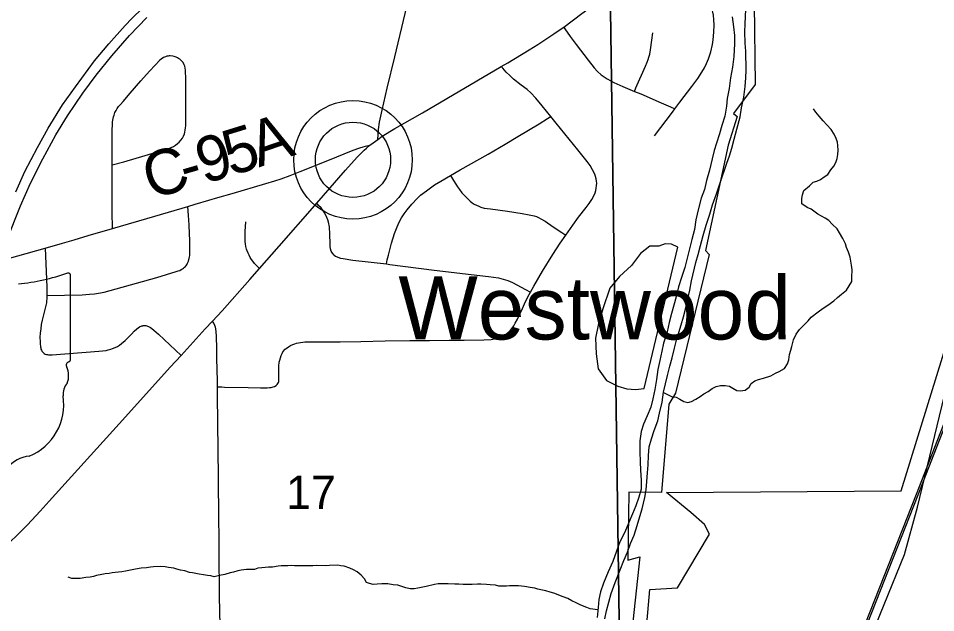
# Model space of a CAD drawing. Extents: x 0 to 34, y 0 to 22.
# Drawn here: x 18.513 to 19.665, y 11.815 to 12.561 of the extents above; entities that cross this region are included whole.
import ezdxf

# ---------------------------------------------------------------- set-up
doc = ezdxf.new("R2010")
doc.units = 0
for name, color, linetype in [('GM_X_Corporation', 7, 'Continuous'), ('GM_X_County_Road', 7, 'Continuous'), ('GM_X_County_Road_Text', 7, 'Continuous'), ('GM_X_Major_River', 7, 'Continuous'), ('GM_X_Minor_Lake', 7, 'Continuous'), ('GM_X_Minor_River', 7, 'Continuous'), ('GM_X_Rail_Line', 7, 'Continuous'), ('GM_X_Section', 7, 'Continuous'), ('GM_X_Section_Text', 7, 'Continuous'), ('GM_X_State_Route', 7, 'Continuous'), ('GM_X_State_Shield', 7, 'Continuous'), ('GM_X_Township_Road', 7, 'Continuous'), ('GM_X_Unincorporated', 7, 'Continuous'), ('GM_X_Unincorporated_Location', 7, 'Continuous'), ('GM_X_Unincorporated_Text', 7, 'Continuous')]:
    doc.layers.add(name, color=color, linetype=linetype)

msp = doc.modelspace()

# ---------------------------------------------------------------- linework, layer by layer
at = {"layer": 'GM_X_Corporation'}
for points in [[(19.4365, 12.5791), (19.4378, 12.4781), (19.4109, 12.4418), (19.4155, 12.438), (19.404, 12.4018), (19.3756, 12.2698), (19.38, 12.2645), (19.338, 12.0907), (19.3296, 12.0768), (19.3202, 11.9662), (19.2795, 11.9663), (19.278, 11.8812), (19.2931, 11.8855), (19.2621, 11.5978)], [(19.2866, 11.6238), (19.3057, 11.8444), (19.3404, 11.8464), (19.3805, 11.9139), (19.3744, 11.9259), (19.357, 11.9408), (19.3266, 11.9659), (19.6212, 11.9681), (19.6857, 12.1764)]]:
    msp.add_lwpolyline(points, dxfattribs=at)
at = {"layer": 'GM_X_County_Road'}
msp.add_line((18.4879, 12.2563), (18.5465, 12.2726), dxfattribs=at)
for points in [[(18.9641, 12.409), (18.9645, 12.4151), (18.9649, 12.4214), (18.9663, 12.4307), (18.9695, 12.446), (18.9758, 12.4733), (18.9854, 12.5127), (18.9986, 12.567), (19.0077, 12.6063)], [(19.1975, 12.55), (19.2204, 12.567), (19.2504, 12.5891), (19.2598, 12.5956), (19.2682, 12.6011), (19.2718, 12.6032)], [(19.1192, 12.5006), (19.1273, 12.5054), (19.1542, 12.5215), (19.165, 12.5284), (19.1738, 12.5339), (19.1852, 12.5415), (19.1968, 12.5495), (19.1975, 12.55)], [(18.9641, 12.409), (18.9698, 12.413), (18.9857, 12.4226), (19.0202, 12.4426), (19.1192, 12.5006)], [(18.954, 12.4017), (18.9583, 12.4049), (18.9641, 12.409)], [(18.7255, 12.325), (18.7348, 12.3277), (18.7519, 12.3329), (18.7635, 12.3362), (18.7813, 12.3414), (18.8236, 12.3536), (18.835, 12.357), (18.8427, 12.3596), (18.8543, 12.3639), (18.8668, 12.3687), (18.9015, 12.3825), (18.9332, 12.3954), (18.9414, 12.3984), (18.9459, 12.3999), (18.9487, 12.4006), (18.954, 12.4017)], [(18.8875, 12.329), (18.9236, 12.3706), (18.9383, 12.3867), (18.9425, 12.3912), (18.9446, 12.3932), (18.9471, 12.3955), (18.95, 12.3983), (18.954, 12.4017)], [(18.631, 12.2974), (18.6842, 12.3129), (18.7255, 12.325)], [(18.8155, 12.247), (18.8403, 12.2753), (18.8851, 12.3262), (18.8875, 12.329)], [(18.5465, 12.2726), (18.5682, 12.2789), (18.5831, 12.2832), (18.6006, 12.2885), (18.631, 12.2974)], [(18.7567, 12.1812), (18.7686, 12.1941), (18.8036, 12.2335), (18.8155, 12.247)], [(18.7171, 12.1378), (18.7476, 12.1713), (18.7567, 12.1812)], [(18.2625, 11.683), (18.2699, 11.6903), (18.3514, 11.7649), (18.4086, 11.8174), (18.4384, 11.8446), (18.5022, 11.9035), (18.5117, 11.9129), (18.5242, 11.9253), (18.5401, 11.9425), (18.5514, 11.9551), (18.6473, 12.061), (18.7036, 12.1231), (18.7171, 12.1378)]]:
    msp.add_lwpolyline(points, dxfattribs=at)
at = {"layer": 'GM_X_Major_River'}
for points in [[(19.2491, 11.8073), (19.2513, 11.8176), (19.2543, 11.8286), (19.2572, 11.8392), (19.262, 11.8529), (19.2684, 11.8689), (19.2732, 11.8807), (19.2777, 11.8913), (19.2814, 11.902), (19.2859, 11.9123), (19.2896, 11.9248), (19.2933, 11.9358), (19.2959, 11.9457), (19.2996, 11.9598), (19.301, 11.9693), (19.3021, 11.9799), (19.3028, 11.9905), (19.3034, 12.0008), (19.3041, 12.0125), (19.3048, 12.0235), (19.3078, 12.0334), (19.3111, 12.0437), (19.3156, 12.0558), (19.3178, 12.0657), (19.3211, 12.0794), (19.3229, 12.0919), (19.3255, 12.1022), (19.3277, 12.1128), (19.3306, 12.1246), (19.3336, 12.1352), (19.3365, 12.147), (19.3391, 12.1573), (19.345, 12.1763), (19.348, 12.1865), (19.3509, 12.1979), (19.3535, 12.209), (19.3557, 12.22), (19.3579, 12.2317), (19.3634, 12.2545), (19.3664, 12.2648), (19.3693, 12.2758), (19.3727, 12.2884), (19.3764, 12.3013), (19.3812, 12.3154), (19.3845, 12.3268), (19.3893, 12.3408), (19.3934, 12.3534), (19.4023, 12.3792), (19.4057, 12.3887), (19.4086, 12.3982), (19.4116, 12.4093), (19.4149, 12.4218), (19.419, 12.4374), (19.4208, 12.4488), (19.4237, 12.4621), (19.4255, 12.4757), (19.4262, 12.4864), (19.4265, 12.4962), (19.4264, 12.5197), (19.4252, 12.53), (19.4251, 12.544), (19.4254, 12.5542), (19.4264, 12.5721)], [(19.409, 12.5628), (19.4106, 12.5503), (19.4118, 12.5397), (19.4119, 12.5291), (19.4113, 12.5132), (19.4095, 12.4999), (19.4069, 12.4862), (19.4051, 12.4729), (19.4029, 12.4604), (19.4018, 12.4509), (19.3997, 12.4384), (19.3959, 12.4266), (19.393, 12.4163), (19.3893, 12.4045), (19.3863, 12.395), (19.3841, 12.3848), (19.3804, 12.3703), (19.3767, 12.3574)], [(19.3767, 12.3574), (19.3742, 12.3464), (19.3701, 12.3354), (19.3667, 12.3225), (19.3634, 12.308), (19.3616, 12.2962), (19.3583, 12.2833), (19.3498, 12.2484), (19.3454, 12.2358), (19.3417, 12.224), (19.3387, 12.2115), (19.3358, 12.2012), (19.3328, 12.1906), (19.3299, 12.1792), (19.3273, 12.1678), (19.3228, 12.1534), (19.3206, 12.1435), (19.3181, 12.1317), (19.3159, 12.1203), (19.3141, 12.1078), (19.3119, 12.0953), (19.3093, 12.0835), (19.3071, 12.0732), (19.3023, 12.0622), (19.2978, 12.0519), (19.2948, 12.0424), (19.293, 12.031), (19.2931, 12.017), (19.2936, 12.0045), (19.294, 11.9942), (19.2949, 11.9814), (19.2946, 11.9704), (19.292, 11.9601), (19.2879, 11.9494), (19.2838, 11.9392), (19.2793, 11.9285), (19.2741, 11.9163), (19.2681, 11.9042), (19.2637, 11.8924), (19.2592, 11.8794), (19.2532, 11.8665), (19.2477, 11.8524), (19.2439, 11.8414), (19.2417, 11.8319), (19.2407, 11.8217), (19.2396, 11.8091)]]:
    msp.add_lwpolyline(points, dxfattribs=at)
at = {"layer": 'GM_X_Minor_Lake'}
for points in [[(19.3409, 12.2737), (19.333, 12.2778), (19.325, 12.2781), (19.3171, 12.2751), (19.3057, 12.275), (19.294, 12.2658), (19.2828, 12.2509), (19.2677, 12.2371), (19.2553, 12.2226), (19.2468, 12.1964), (19.2409, 12.1759), (19.2376, 12.1595), (19.2381, 12.1402), (19.2409, 12.1213), (19.2512, 12.1066), (19.2653, 12.0995), (19.277, 12.0961), (19.2876, 12.0954), (19.2986, 12.0967)], [(19.2986, 12.0967), (19.3409, 12.2737)]]:
    msp.add_lwpolyline(points, dxfattribs=at)
at = {"layer": 'GM_X_Minor_River'}
for points in [[(19.3228, 12.0917), (19.3337, 12.0859), (19.3387, 12.0856), (19.3433, 12.0833), (19.3483, 12.0804), (19.3532, 12.0789), (19.3578, 12.0801), (19.3634, 12.0832), (19.3687, 12.0863), (19.3733, 12.0898), (19.3789, 12.0929), (19.3838, 12.0964), (19.3891, 12.0991), (19.3944, 12.1004), (19.4001, 12.1004), (19.4055, 12.0994), (19.41, 12.0971), (19.415, 12.0942), (19.4196, 12.0935), (19.4253, 12.0943), (19.4302, 12.0982), (19.4328, 12.1028), (19.4373, 12.1062), (19.4422, 12.1078), (19.4483, 12.1094), (19.4574, 12.1126), (19.4634, 12.1157), (19.468, 12.1177), (19.4748, 12.1216), (19.4785, 12.1273), (19.4803, 12.1327), (19.481, 12.1391), (19.4828, 12.1448), (19.4839, 12.1494), (19.4861, 12.1574), (19.4894, 12.1647), (19.4935, 12.1704), (19.5044, 12.1816), (19.5082, 12.1862), (19.5172, 12.1928), (19.5232, 12.1974), (19.5293, 12.2009), (19.5368, 12.2067), (19.5413, 12.2106), (19.5462, 12.2148), (19.5526, 12.2198), (19.5593, 12.2306), (19.5592, 12.2363), (19.5595, 12.2454), (19.559, 12.2515), (19.557, 12.2613), (19.555, 12.2677), (19.5527, 12.2734), (19.5515, 12.2779), (19.548, 12.2847), (19.5437, 12.2919), (19.541, 12.2968), (19.5344, 12.3028), (19.5305, 12.3073), (19.5259, 12.3103), (19.5213, 12.3129), (19.5164, 12.3151), (19.5083, 12.3214), (19.503, 12.3236), (19.4964, 12.3281), (19.4967, 12.335), (19.4974, 12.3395), (19.4992, 12.3452), (19.506, 12.351), (19.5109, 12.3553), (19.5155, 12.3569), (19.52, 12.3588), (19.5245, 12.3623), (19.529, 12.365), (19.5331, 12.3708), (19.5365, 12.3754), (19.5391, 12.3803), (19.5409, 12.3853), (19.5416, 12.3903), (19.5423, 12.3956), (19.5419, 12.4013), (19.5411, 12.4058), (19.5395, 12.4104), (19.5371, 12.4156), (19.5332, 12.4217), (19.5278, 12.4273), (19.5232, 12.4326), (19.5182, 12.4382), (19.514, 12.4431), (19.5112, 12.4476)], [(19.2404, 11.8188), (19.2307, 11.8201), (19.2265, 11.8216), (19.2189, 11.8245), (19.2131, 11.8275), (19.2078, 11.8301), (19.2028, 11.833), (19.1967, 11.8352), (19.1852, 11.8396), (19.1806, 11.8411), (19.1753, 11.8426), (19.1711, 11.8433), (19.165, 11.8447), (19.1612, 11.8458), (19.1554, 11.8468), (19.1482, 11.8479), (19.1406, 11.8489), (19.1295, 11.8488), (19.1257, 11.8484), (19.1208, 11.8483), (19.1162, 11.8486), (19.112, 11.8497), (19.1052, 11.85), (19.1006, 11.8507), (19.0934, 11.851), (19.0892, 11.8509), (19.0827, 11.8504), (19.0759, 11.8507), (19.0713, 11.8507), (19.066, 11.851), (19.0607, 11.8509), (19.0523, 11.8516), (19.0401, 11.8514), (19.0352, 11.8506), (19.025, 11.8481), (19.0185, 11.8469), (19.0143, 11.8461), (19.0098, 11.8453), (19.0048, 11.8452), (18.9995, 11.8463), (18.9942, 11.8481), (18.9892, 11.8496), (18.9835, 11.8503), (18.9766, 11.8513), (18.9728, 11.8513), (18.969, 11.8516), (18.9633, 11.8511), (18.9584, 11.8507), (18.9538, 11.8518), (18.95, 11.8532), (18.9473, 11.8577), (18.9434, 11.8623), (18.9384, 11.8664), (18.9338, 11.869), (18.9292, 11.8712), (18.9219, 11.8734), (18.9178, 11.8741), (18.9139, 11.8748), (18.9037, 11.8746), (18.8987, 11.8742), (18.8873, 11.8744), (18.8824, 11.874), (18.8729, 11.8739), (18.8664, 11.8741), (18.8596, 11.8741), (18.8558, 11.8744), (18.8512, 11.8739), (18.8428, 11.8738), (18.839, 11.8734), (18.8318, 11.8725), (18.8269, 11.8725), (18.8185, 11.8716), (18.8136, 11.8712), (18.8094, 11.8696), (18.7992, 11.8694), (18.7927, 11.8686), (18.7885, 11.8678), (18.7828, 11.8662), (18.7787, 11.8654), (18.7719, 11.863), (18.7654, 11.8618), (18.7586, 11.8602), (18.7544, 11.8613), (18.7502, 11.862), (18.7452, 11.8627), (18.7399, 11.8637), (18.7315, 11.8651), (18.7277, 11.8658), (18.722, 11.8677), (18.7163, 11.8687), (18.7117, 11.8698), (18.7079, 11.8709), (18.7014, 11.8719), (18.6972, 11.8726), (18.6915, 11.873), (18.6827, 11.8728), (18.6786, 11.8724)], [(18.6786, 11.8724), (18.6736, 11.8716), (18.6672, 11.8711), (18.66, 11.8699), (18.6474, 11.8674), (18.6429, 11.8666), (18.6387, 11.8662), (18.6345, 11.8657), (18.6307, 11.8653), (18.6269, 11.8645), (18.622, 11.864), (18.6178, 11.8632), (18.611, 11.862), (18.6072, 11.8608), (18.603, 11.8596), (18.5977, 11.8592), (18.5905, 11.8583), (18.5802, 11.8582), (18.5753, 11.8596)]]:
    msp.add_lwpolyline(points, dxfattribs=at)
at = {"layer": 'GM_X_Rail_Line'}
for points in [[(18.7784, 9.1775), (18.7977, 9.2424), (18.8168, 9.3375), (18.9298, 9.894), (18.9918, 10.216), (19.0166, 10.3387), (19.0457, 10.4205), (19.1061, 10.5746), (19.3565, 11.2099), (19.4976, 11.5746), (19.6255, 11.8884), (19.6416, 11.9475), (19.8022, 12.6107)], [(19.3502, 11.2278), (19.6405, 11.9641), (19.7617, 12.2746)], [(19.3524, 11.227), (19.6427, 11.9632), (19.7639, 12.2737)]]:
    msp.add_lwpolyline(points, dxfattribs=at)
at = {"layer": 'GM_X_Section'}
for points in [[(18.2539, 12.6075), (19.256, 12.6012), (19.2699, 11.5992), (18.2587, 11.5914)], [(19.256, 12.6012), (20.265, 12.6049), (20.27, 11.6062), (19.2699, 11.5992)]]:
    msp.add_lwpolyline(points, close=True, dxfattribs=at)
at = {"layer": 'GM_X_State_Route'}
for points in [[(18.5095, 12.3434), (18.5211, 12.3687), (18.5367, 12.3991), (18.5504, 12.4234), (18.5685, 12.4523), (18.5845, 12.4752), (18.6086, 12.5075), (18.6263, 12.529), (18.647, 12.552), (18.6554, 12.5608), (18.6686, 12.5739)], [(18.4983, 12.2825), (18.5156, 12.3258), (18.5281, 12.3543), (18.5434, 12.3849), (18.5599, 12.415), (18.5746, 12.4388), (18.5938, 12.4671), (18.6105, 12.4896), (18.6301, 12.5138), (18.6526, 12.5395), (18.674, 12.5621)]]:
    msp.add_lwpolyline(points, dxfattribs=at)
at = {"layer": 'GM_X_State_Shield'}
for q in [(18.5783, 12.2381), (18.5783, 12.1334)]:
    msp.add_line((18.5783, 12.1334), q, dxfattribs=at)
for centre, radius, start, end in [((18.4844, 12.506), 0.2796, 275.8445, 288.9065), ((18.5754, 12.2385), 0.00294, 351.8621, 97.738), ((18.5776, 12.1257), 0.00454, 107.944, 210.337), ((18.5752, 12.133), 0.00314, 289.6038, 7.7341), ((18.5487, 12.1125), 0.0273, 340.033, 23.6496), ((18.5888, 12.0896), 0.0198, 136.8065, 186.9296), ((18.5, 12.0763), 0.0699, 292.3089, 8.9858), ((18.5295, 11.9734), 0.0383, 94.4031, 142.5768)]:
    msp.add_arc(centre, radius, start, end, dxfattribs=at)
at = {"layer": 'GM_X_Township_Road'}
for points in [[(19.3371, 12.4475), (19.3435, 12.4558), (19.3586, 12.4756), (19.3658, 12.4856), (19.371, 12.4934), (19.3741, 12.4988), (19.3769, 12.5044), (19.3792, 12.5101), (19.3821, 12.519), (19.3843, 12.5281), (19.3853, 12.5342), (19.3862, 12.5435), (19.3865, 12.5529), (19.3862, 12.5591), (19.3854, 12.5652), (19.3835, 12.5744), (19.3811, 12.5834), (19.3782, 12.5923), (19.3681, 12.6184), (19.3635, 12.6305), (19.3603, 12.6389), (19.3591, 12.6418)], [(19.1975, 12.55), (19.1989, 12.5479), (19.2057, 12.5381), (19.2131, 12.5282), (19.2281, 12.5086), (19.2359, 12.499), (19.2401, 12.4945), (19.2446, 12.4903), (19.2471, 12.4884), (19.2523, 12.4851), (19.2565, 12.4827), (19.2604, 12.4807), (19.2717, 12.4757), (19.2865, 12.4694)], [(19.2865, 12.4694), (19.2883, 12.4737), (19.3002, 12.501), (19.3022, 12.5062), (19.3035, 12.5093), (19.3043, 12.5121), (19.3055, 12.5162), (19.3066, 12.5214), (19.3082, 12.5336), (19.3094, 12.5427)], [(18.6308, 12.377), (18.6451, 12.381), (18.6987, 12.3969), (18.7017, 12.3979), (18.7048, 12.399), (18.7076, 12.4004), (18.7101, 12.4018), (18.7128, 12.4039), (18.7148, 12.4058), (18.717, 12.408), (18.7188, 12.4105), (18.7203, 12.4132), (18.7215, 12.4159), (18.722, 12.418), (18.7225, 12.4206), (18.7229, 12.4236), (18.723, 12.4263), (18.723, 12.4302), (18.7231, 12.4688), (18.723, 12.4874), (18.7229, 12.4932), (18.7227, 12.4959), (18.7223, 12.4986), (18.7217, 12.501), (18.721, 12.5027), (18.7196, 12.5055), (18.7177, 12.5079), (18.7165, 12.5091), (18.7154, 12.51), (18.714, 12.5108), (18.7127, 12.5116), (18.7112, 12.5123), (18.7098, 12.5128), (18.7084, 12.5132), (18.7068, 12.5135), (18.7034, 12.5138), (18.7022, 12.5138), (18.7011, 12.5137), (18.6993, 12.5134), (18.6977, 12.5129), (18.6962, 12.5123), (18.6949, 12.5117), (18.6923, 12.51), (18.6901, 12.5081)], [(18.6308, 12.377), (18.6308, 12.4212), (18.6309, 12.4276), (18.6311, 12.4311), (18.6313, 12.4334), (18.6317, 12.4353), (18.6322, 12.4374), (18.633, 12.4397), (18.6341, 12.4427), (18.6355, 12.4454), (18.637, 12.4478), (18.6388, 12.4502), (18.641, 12.453), (18.6443, 12.4568), (18.6533, 12.467), (18.6668, 12.4824), (18.6777, 12.4948), (18.6845, 12.5021), (18.6901, 12.5081)], [(19.1812, 12.438), (19.1705, 12.4514), (19.1626, 12.4609), (19.1561, 12.4676), (19.1515, 12.4717), (19.1441, 12.4773), (19.1343, 12.4849), (19.1297, 12.4891), (19.1255, 12.4936), (19.1213, 12.4983), (19.1192, 12.5006)], [(19.2865, 12.4694), (19.2945, 12.4661), (19.3199, 12.4551), (19.3317, 12.4499), (19.3371, 12.4475)], [(19.0554, 12.3638), (19.0675, 12.3708), (19.1025, 12.3907), (19.1239, 12.4033), (19.1398, 12.4128), (19.1666, 12.4285), (19.177, 12.4353), (19.1812, 12.438)], [(19.2001, 12.2891), (19.2088, 12.3015), (19.2162, 12.3115), (19.2257, 12.3237), (19.2293, 12.3287), (19.2327, 12.3339), (19.2357, 12.3393), (19.2369, 12.3422), (19.2379, 12.3451), (19.2385, 12.3481), (19.2389, 12.3512), (19.239, 12.3543), (19.2389, 12.3566), (19.2384, 12.3596), (19.2376, 12.3626), (19.2365, 12.3655), (19.2338, 12.3711), (19.2307, 12.3765), (19.2271, 12.3815), (19.2154, 12.396), (19.188, 12.4296), (19.1812, 12.438)], [(19.3117, 12.4135), (19.334, 12.4434), (19.3371, 12.4475)], [(18.631, 12.2974), (18.6307, 12.3183), (18.6308, 12.362), (18.6308, 12.377)], [(18.9749, 12.2528), (18.9761, 12.258), (18.9775, 12.264), (18.9815, 12.279), (18.9852, 12.2909), (18.9885, 12.2996), (18.9911, 12.3052), (18.994, 12.3107), (18.9974, 12.3159), (19.0011, 12.3209), (19.007, 12.328), (19.0134, 12.3348), (19.0179, 12.339), (19.0253, 12.3447), (19.0354, 12.3519), (19.0433, 12.3568), (19.0554, 12.3638)], [(19.0554, 12.3638), (19.059, 12.3576), (19.062, 12.3528), (19.0643, 12.3495), (19.0666, 12.3461), (19.0697, 12.3421), (19.0758, 12.3357), (19.0803, 12.3315), (19.0827, 12.3296), (19.0853, 12.3279), (19.088, 12.3264), (19.0908, 12.3252), (19.0937, 12.3242), (19.0976, 12.323), (19.1016, 12.3224), (19.1057, 12.3218), (19.127, 12.319), (19.1453, 12.3163), (19.1543, 12.3146), (19.1603, 12.3132), (19.1632, 12.3122), (19.166, 12.311), (19.1688, 12.3096), (19.1741, 12.3065), (19.1842, 12.2996), (19.1951, 12.2924), (19.2001, 12.2891)], [(18.5487, 12.2133), (18.5929, 12.2142), (18.6022, 12.2147), (18.6084, 12.2153), (18.6134, 12.2161), (18.6207, 12.2175), (18.6357, 12.2214), (18.6867, 12.2357), (18.7111, 12.2432), (18.7136, 12.2441), (18.7155, 12.2448), (18.7172, 12.2457), (18.719, 12.2467), (18.7204, 12.2476), (18.7216, 12.2487), (18.7229, 12.2498), (18.7241, 12.2514), (18.7247, 12.2524), (18.7254, 12.2537), (18.7264, 12.2564), (18.727, 12.2582), (18.7273, 12.2596), (18.7277, 12.2616), (18.728, 12.2636), (18.728, 12.2656), (18.7281, 12.272), (18.728, 12.2827), (18.7278, 12.2907), (18.7273, 12.3019), (18.7264, 12.3135), (18.7255, 12.325)], [(18.9092, 12.2638), (18.9073, 12.2663), (18.9057, 12.2689), (18.9049, 12.2719), (18.9045, 12.2749), (18.9043, 12.2779), (18.9041, 12.2903), (18.9035, 12.2994), (18.9023, 12.3054), (18.9014, 12.3083), (18.9002, 12.3112), (18.8975, 12.3167), (18.8958, 12.3192), (18.8929, 12.3231), (18.8899, 12.3263), (18.8875, 12.329)], [(18.8155, 12.247), (18.8095, 12.2534), (18.8074, 12.2562), (18.8057, 12.2585), (18.804, 12.261), (18.8025, 12.2637), (18.8013, 12.2664), (18.8001, 12.2694), (18.7993, 12.2714), (18.7989, 12.2731), (18.7986, 12.2747), (18.7981, 12.2779), (18.7978, 12.2808), (18.7976, 12.2845), (18.7975, 12.2937), (18.7985, 12.3058)], [(19.1557, 12.2174), (19.1599, 12.2251), (19.171, 12.2439), (19.184, 12.2648), (19.193, 12.2788), (19.2001, 12.2891)], [(18.5465, 12.2726), (18.5485, 12.2239), (18.5487, 12.2133)], [(18.9092, 12.2638), (18.9112, 12.2625), (18.9141, 12.2612), (18.9173, 12.2602), (18.9206, 12.2595), (18.933, 12.2577), (18.9749, 12.2528)], [(18.9749, 12.2528), (18.9794, 12.2522), (19.0351, 12.2451), (19.0815, 12.2397), (19.1032, 12.237), (19.1155, 12.2352), (19.1216, 12.2338), (19.1275, 12.232), (19.1333, 12.2296), (19.1388, 12.2268), (19.1497, 12.2208), (19.1557, 12.2174)], [(18.5487, 12.2133), (18.5487, 12.2115), (18.5486, 12.2089), (18.5483, 12.2065), (18.548, 12.2042), (18.5467, 12.1972), (18.5426, 12.1823), (18.5415, 12.1768), (18.5409, 12.1715), (18.5404, 12.166), (18.54, 12.161), (18.5401, 12.1551), (18.5403, 12.1519), (18.5405, 12.1501), (18.5407, 12.1489), (18.5409, 12.1474), (18.5413, 12.146), (18.5418, 12.1448), (18.5425, 12.1434), (18.5435, 12.1421), (18.5443, 12.1414), (18.5452, 12.1406), (18.5466, 12.1398), (18.5481, 12.1393), (18.5494, 12.139), (18.5508, 12.1388), (18.5532, 12.1388), (18.5554, 12.1387), (18.6139, 12.1432), (18.623, 12.1444), (18.6257, 12.145), (18.6289, 12.1459), (18.631, 12.1466), (18.6345, 12.148), (18.6372, 12.1494), (18.6398, 12.151), (18.6424, 12.1531), (18.6468, 12.1568), (18.6549, 12.1649), (18.6584, 12.1685), (18.6615, 12.1712), (18.6633, 12.1726), (18.665, 12.1738), (18.6659, 12.1743), (18.6671, 12.1748), (18.668, 12.1751), (18.669, 12.1753), (18.6697, 12.1754), (18.6704, 12.1755)], [(18.8378, 12.1014), (18.8387, 12.1027), (18.8393, 12.104), (18.8397, 12.1055), (18.84, 12.1078), (18.84, 12.1135), (18.84, 12.1167), (18.84, 12.122), (18.84, 12.1246), (18.8405, 12.1295), (18.841, 12.1322), (18.8418, 12.135), (18.8428, 12.1379), (18.8441, 12.1406), (18.8451, 12.1425), (18.848, 12.1458), (18.8492, 12.1469), (18.8521, 12.149), (18.8546, 12.1506), (18.8573, 12.1517), (18.8599, 12.1527), (18.8621, 12.1534), (18.8644, 12.1539), (18.8671, 12.1544), (18.8699, 12.1548), (18.8727, 12.1551), (18.8757, 12.1551), (18.8846, 12.1551), (18.8994, 12.1552), (18.9025, 12.1551), (18.9171, 12.1551), (18.9428, 12.1556), (18.9734, 12.1562), (19.0044, 12.1566), (19.0291, 12.1568), (19.0538, 12.1571), (19.0724, 12.1573), (19.0972, 12.1576), (19.1065, 12.1581), (19.1126, 12.1591), (19.1156, 12.1599), (19.1185, 12.161), (19.1212, 12.1622), (19.1237, 12.1637), (19.1263, 12.1656), (19.1288, 12.1678), (19.1308, 12.1699), (19.1329, 12.1724), (19.1349, 12.1753), (19.1367, 12.1785), (19.1395, 12.1836), (19.1457, 12.1969), (19.1482, 12.2028), (19.1525, 12.2115), (19.1557, 12.2174)], [(18.6704, 12.1755), (18.6712, 12.1755), (18.673, 12.1754), (18.6743, 12.1751), (18.6752, 12.1748), (18.6762, 12.1745), (18.6773, 12.174), (18.6786, 12.1732), (18.6804, 12.1719), (18.6829, 12.1698), (18.6887, 12.1649), (18.6961, 12.1581), (18.7171, 12.1378)], [(18.763, 12.0987), (18.7629, 12.1063), (18.7622, 12.1343), (18.7622, 12.1437), (18.7621, 12.1466), (18.7617, 12.162), (18.7614, 12.1677), (18.7609, 12.1714), (18.7603, 12.1737), (18.7597, 12.1754), (18.7581, 12.1785), (18.7567, 12.1812)], [(18.763, 12.0987), (18.7685, 12.0985), (18.7715, 12.0984), (18.8015, 12.0977), (18.8167, 12.0974), (18.8253, 12.0975), (18.8283, 12.0976), (18.8304, 12.0979), (18.8326, 12.0985), (18.8346, 12.0992), (18.8364, 12.1002), (18.8378, 12.1014)], [(18.7696, 11.5556), (18.7691, 11.5689), (18.7684, 11.5937), (18.7681, 11.6123), (18.768, 11.631), (18.768, 11.6372), (18.7679, 11.6403), (18.7675, 11.6714), (18.7673, 11.6931), (18.7671, 11.7149), (18.7665, 11.7708), (18.7661, 11.7988), (18.7655, 11.836), (18.7652, 11.8546), (18.765, 11.8733), (18.7649, 11.8888), (18.7649, 11.9105), (18.7647, 11.9323), (18.7641, 11.9851), (18.763, 12.0877), (18.763, 12.0987)]]:
    msp.add_lwpolyline(points, dxfattribs=at)
at = {"layer": 'GM_X_Unincorporated'}
for radius in [0.0744, 0.0472]:
    msp.add_circle((18.933, 12.3835), radius, dxfattribs=at)
at = {"layer": 'GM_X_Unincorporated_Location'}
msp.add_line((18.933, 12.3835), (18.933, 12.3835), dxfattribs=at)

# ---------------------------------------------------------------- texts
at = {"layer": 'GM_X_County_Road_Text'}
for s, rotation, p in [('5', 17.0783, (18.7797, 12.363)), ('A', 18.8961, (18.8147, 12.3738)), ('9', 16.3353, (18.7456, 12.353)), ('C', 16.304, (18.6789, 12.3335)), ('-', 16.3039, (18.7233, 12.3465))]:
    msp.add_text(s, height=0.0568, rotation=rotation, dxfattribs=at).set_placement(p)
at = {"layer": 'GM_X_Section_Text'}
msp.add_text('17', height=0.04186, rotation=0, dxfattribs=at).set_placement((18.8491, 11.9454))
at = {"layer": 'GM_X_Unincorporated_Text'}
msp.add_text('Westwood', height=0.07898, rotation=0, dxfattribs=at).set_placement((18.99, 12.1581))

doc.saveas('drawing.dxf')
